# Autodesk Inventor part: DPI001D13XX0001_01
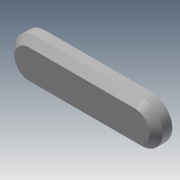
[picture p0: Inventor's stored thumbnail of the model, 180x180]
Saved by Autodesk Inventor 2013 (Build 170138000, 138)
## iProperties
Created: 2014-02
Part Number: DPI001D13XX0001_01
Material: ASTM-A 36
Description: CHAPA - 350 x 100 x 1.1/2"
Document SubType Name: Modeling
Designer: luiz.parente
Density: 7.85 g/cm^3
Mass: 6832.52 g
Surface Area: 697.776 cm^2
Volume: 870.385 cm^3
Author: luiz.parente
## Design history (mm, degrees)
sketch "Sketch1"
  geometry: L1 (125, 50)-(-125, 50); L2 (-125, 50)-(-125, -50); L3 (-125, -50)-(125, -50); L4 (125, -50)-(125, 50); L5 (125, 50)-(-125, -50); L6 (-125, 50)-(125, -50); A1 r 50 centre (-125, 0) between (-125, 50) and (-125, -50); A2 r 50 centre (125, 0) between (125, -50) and (125, 50); 1 further point
  constraints: 12 end point, 4 midpoint, 4 point on circle, 2 centre point, 2 parallel, 1 horizontal, 1 perpendicular
  dimensions: "d1" = 100 distance of L1.start L3.end; "d7" = 250 distance of L1.start L1.end
extrude "Extrusion1" new body sketch "Sketch1" distance "d2" = 38.1; taper "d3" = 0 deg
chamfer "Chamfer1" distance "d4" = 15.8; stored, may be unused: second distance "d5" = 2, angle "d6" = 45 deg
body "Solid1"
